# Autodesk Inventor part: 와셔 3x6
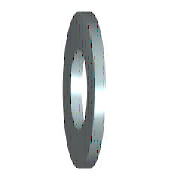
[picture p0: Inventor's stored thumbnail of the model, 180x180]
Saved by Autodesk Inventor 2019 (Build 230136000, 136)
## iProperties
IsCustomPart: 0
Created: 2012-02
Part Number: 와셔 3x6
Material: 강철, 연강
Description: 평면 와셔
Document SubType Name: Modeling
Standard: KS B 1326
Designer: mduedu
Standards Organization: KS
Language: ko-KR
Size Designation: 3x6
Categories: <MemberInstance><Categories><Category DisplayName="조임쇠" InternalName="e4da775c-781d-43d5-af7c-5136215cf5a6" Mnemonic="FSTN"><Category DisplayName="와셔" InternalN
Density: 7.86 g/cm^3
Mass: 0.0795112 g
Surface Area: 0.54915 cm^2
Volume: 0.0101159 cm^3
Appearance: 파란색 - 벽 페인트 - 광택
Author: mduedu
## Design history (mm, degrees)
sketch "스케치"
  geometry: C1 r 3 at (0, 0); C2 r 1.6 at (0, 0); 1 further point
  constraints: 2 centre point, 2 coincident
  dimensions: "d0" = 3.2 diameter of C2 (= SD1); "d1" = 6 diameter of C1 (= SD2)
extrude "본체" new body sketch "스케치" distance "d2" = 0.5 (= SD); taper "d3" = 0 deg
workaxis "Work Axis1"
workplane "Work Plane1"
body "Solid1"
other parameters: "SD1" = 3.2 [user parameter; used in 1 equation term], "SD2" = 6 [user parameter; used in 1 equation term], "SD" = 0.5 [user parameter; used in 1 equation term], "d4" = 0, "d5" = 0, "d6" = 0, "d7" = 0, "NND" = 3 [user parameter]
